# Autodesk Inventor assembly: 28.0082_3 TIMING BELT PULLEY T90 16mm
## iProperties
Created: 2007-04
Part Number: 28.0082_3 TIMING BELT PULLEY T90 16mm
Document SubType Name: Assembly
Designer: Andy Moles
Author: Andy Moles
